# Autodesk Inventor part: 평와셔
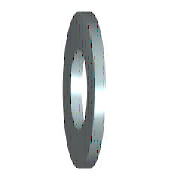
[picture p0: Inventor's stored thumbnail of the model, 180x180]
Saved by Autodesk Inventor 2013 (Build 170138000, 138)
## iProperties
IsCustomPart: 1
Created: 2012-02
Part Number: 평와셔
Material: 강철, 연강
Description: 평면 와셔 - 초대형 시리즈 - 제품 등급 C
Document SubType Name: Modeling
Standard: ISO 7094
Designer: mduedu
Standard Revision: Second edition 2000-06-01
Standards Organization: ISO
Language: ko-KR
Size Designation: ST 5 - 100 HV
Categories: <MemberInstance><Categories><Category DisplayName="조임쇠" InternalName="e4da775c-781d-43d5-af7c-5136215cf5a6" Mnemonic="FSTN"><Category DisplayName="와셔" InternalN
Density: 7.85 g/cm^3
Mass: 3.62216 g
Surface Area: 6.09076 cm^2
Volume: 0.461421 cm^3
Author: mduedu
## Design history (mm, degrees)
sketch "스케치"
  geometry: C1 r 9 at (0, 0); C2 r 2.75 at (0, 0); 1 further point
  constraints: 2 centre point, 2 coincident
  dimensions: "d0" = 5.5 diameter of C2 (= SD1); "d1" = 18 diameter of C1 (= SD2)
extrude "본체" new body sketch "스케치" distance "d2" = 2 (= SD); taper "d3" = 0 deg
workaxis "Work Axis1"
workplane "Work Plane1"
body "Solid1"
other parameters: "SD1" = 5.5 [user parameter; used in 1 equation term], "SD2" = 18 [user parameter; used in 1 equation term], "SD" = 2 [user parameter; used in 1 equation term], "d4" = 0, "d5" = 0, "d6" = 0, "d7" = 0, "NND" = 5 [user parameter]
